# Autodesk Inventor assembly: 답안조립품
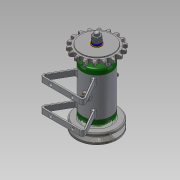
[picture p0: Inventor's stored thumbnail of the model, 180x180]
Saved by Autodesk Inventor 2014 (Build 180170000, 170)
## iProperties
Created: 2016-03
Part Number: 답안조립품
Document SubType Name: Assembly
Designer: user
Author: user
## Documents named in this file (16)
- C:\Users\user\Desktop\460308V1007\답안조립품.iam
- C:\Users\user\Desktop\460308V1007\V벨트풀리.ipt
- C:\Users\user\Desktop\460308V1007\너트 M 8.ipt
- C:\Users\user\Desktop\460308V1007\니플 M 6 x 0.75.ipt
- C:\Users\user\Desktop\460308V1007\베어링 15 x 32 x 9.ipt
- C:\Users\user\Desktop\460308V1007\본체.ipt
- C:\Users\user\Desktop\460308V1007\볼트 M 6 x 8.ipt
- C:\Users\user\Desktop\460308V1007\볼트 M4 x 12.ipt
- C:\Users\user\Desktop\460308V1007\스프로킷.ipt
- C:\Users\user\Desktop\460308V1007\스프링와셔 8.ipt
- C:\Users\user\Desktop\460308V1007\오일 실 15 25 7.ipt
- C:\Users\user\Desktop\460308V1007\와셔 6x11.5.ipt
- C:\Users\user\Desktop\460308V1007\와셔 8x17.ipt
- C:\Users\user\Desktop\460308V1007\축.ipt
- C:\Users\user\Desktop\460308V1007\커버.ipt
- C:\Users\user\Desktop\460308V1007\키 3 x 3 x 12.ipt
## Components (11 placed, 3 different names)
1. V벨트풀리:1 — Mate:28, Mate:29, Mate:30, Mate:32
2. KS B 2023 6002 - 15 x 32 x 9:1 — Mate:5, Mate:6
3. KS B 2023 6002 - 15 x 32 x 9:2 — Mate:3, Mate:4, Mate:10, Mate:54
4. ISO 4762 M4 x 12:1 — Mate:15, Mate:16
5. ISO 4762 M4 x 12:3
6. ISO 4762 M4 x 12:4
7. ISO 4762 M4 x 12:5
8. ISO 4762 M4 x 12:2 — Mate:17, Mate:18
9. ISO 4762 M4 x 12:6
10. ISO 4762 M4 x 12:7
11. ISO 4762 M4 x 12:8
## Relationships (14: Mate 14)
- Mate:3: KS B 2023 6002 - 15 x 32 x 9:2
- Mate:4: KS B 2023 6002 - 15 x 32 x 9:2
- Mate:5: KS B 2023 6002 - 15 x 32 x 9:1
- Mate:6: KS B 2023 6002 - 15 x 32 x 9:1
- Mate:10: KS B 2023 6002 - 15 x 32 x 9:2
- Mate:15: ISO 4762 M4 x 12:1
- Mate:16: ISO 4762 M4 x 12:1
- Mate:17: ISO 4762 M4 x 12:2
- Mate:18: ISO 4762 M4 x 12:2
- Mate:28: V벨트풀리:1
- Mate:29: V벨트풀리:1
- Mate:30: V벨트풀리:1
- Mate:32: V벨트풀리:1
- Mate:54: KS B 2023 6002 - 15 x 32 x 9:2
## Named parameters: d6_d0 = 0, d7_d1 = 0
